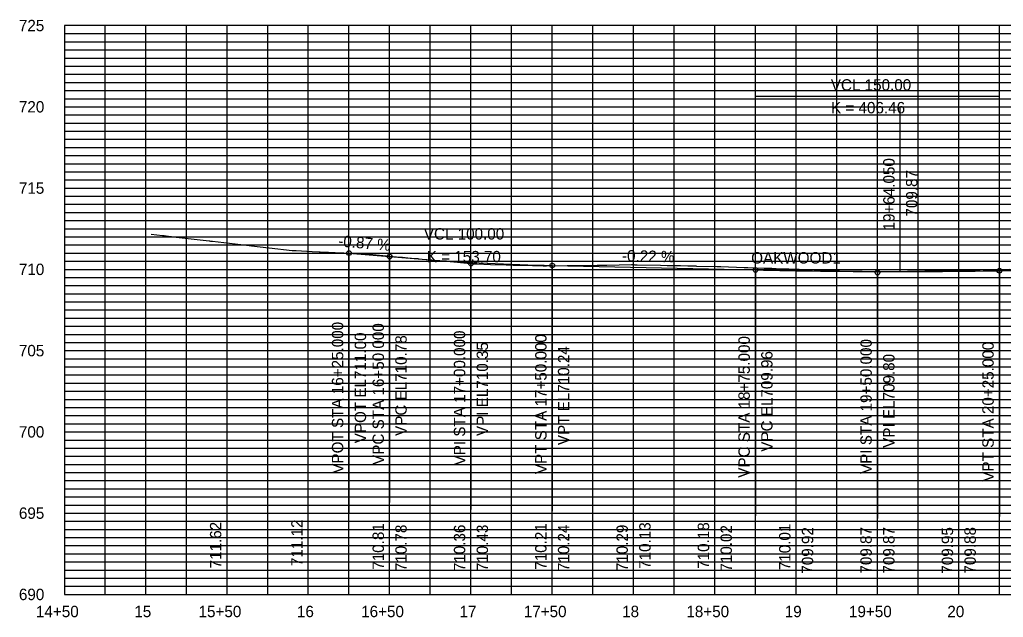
# Model space of a CAD drawing. Extents: x 599407 to 600507, y 234180 to 234548.
# Drawn here: x 599407 to 600012, y 234180 to 234548 of the extents above; entities that cross this region are included whole.
import ezdxf

# ---------------------------------------------------------------- set-up
doc = ezdxf.new("R2010")
doc.units = 0
for name, color, linetype in [('E_PROF_Grid', 7, 'Continuous'), ('E_PROF_GridMin', 7, 'Continuous'), ('P_E_XS_Ground', 7, 'Continuous'), ('P_PROF', 7, 'Continuous'), ('P_PROF_Grades', 7, 'Continuous'), ('P_PROF_VPINotes', 7, 'Continuous'), ('P_XS_Text', 7, 'Continuous'), ('PLT_Sheet_Info', 7, 'Continuous')]:
    doc.layers.add(name, color=color, linetype=linetype)

msp = doc.modelspace()

# ---------------------------------------------------------------- linework, layer by layer
at = {"layer": 'E_PROF_Grid'}
for p, q in [((599459.31, 234193.96), (599459.31, 234543.96)), ((599484.31, 234193.96), (599484.31, 234543.96)), ((599509.31, 234193.96), (599509.31, 234543.96)), ((599534.31, 234193.96), (599534.31, 234543.96)), ((599559.31, 234193.96), (599559.31, 234543.96)), ((599584.31, 234193.96), (599584.31, 234543.96)), ((599609.31, 234193.96), (599609.31, 234543.96)), ((599634.31, 234193.96), (599634.31, 234543.96)), ((599659.31, 234193.96), (599659.31, 234543.96)), ((599684.31, 234193.96), (599684.31, 234543.96)), ((599709.31, 234193.96), (599709.31, 234543.96)), ((599734.31, 234193.96), (599734.31, 234543.96)), ((599759.31, 234193.96), (599759.31, 234543.96)), ((599784.31, 234193.96), (599784.31, 234543.96)), ((599809.31, 234193.96), (599809.31, 234543.96)), ((599834.31, 234193.96), (599834.31, 234543.96)), ((599859.31, 234193.96), (599859.31, 234543.96)), ((599884.31, 234193.96), (599884.31, 234543.96)), ((599909.31, 234193.96), (599909.31, 234543.96)), ((599934.31, 234193.96), (599934.31, 234543.96)), ((599959.31, 234193.96), (599959.31, 234543.96)), ((599984.31, 234193.96), (599984.31, 234543.96)), ((600009.31, 234193.96), (600009.31, 234543.96)), ((599434.31, 234518.96), (600484.31, 234518.96)), ((599434.31, 234493.96), (600484.31, 234493.96)), ((599434.31, 234468.96), (600484.31, 234468.96)), ((599434.31, 234443.96), (600484.31, 234443.96)), ((599434.31, 234418.96), (600484.31, 234418.96)), ((599434.31, 234393.96), (600484.31, 234393.96)), ((599434.31, 234368.96), (600484.31, 234368.96)), ((599434.31, 234343.96), (600484.31, 234343.96)), ((599434.31, 234318.96), (600484.31, 234318.96)), ((599434.31, 234293.96), (600484.31, 234293.96)), ((599434.31, 234268.96), (600484.31, 234268.96)), ((599434.31, 234243.96), (600484.31, 234243.96)), ((599434.31, 234218.96), (600484.31, 234218.96))]:
    msp.add_line(p, q, dxfattribs=at)
at = {"layer": 'E_PROF_GridMin'}
for p, q in [((599434.31, 234538.96), (600484.31, 234538.96)), ((599434.31, 234533.96), (600484.31, 234533.96)), ((599434.31, 234528.96), (600484.31, 234528.96)), ((599434.31, 234523.96), (600484.31, 234523.96)), ((599434.31, 234513.96), (600484.31, 234513.96)), ((599434.31, 234508.96), (600484.31, 234508.96)), ((599434.31, 234503.96), (600484.31, 234503.96)), ((599434.31, 234498.96), (600484.31, 234498.96)), ((599434.31, 234488.96), (600484.31, 234488.96)), ((599434.31, 234483.96), (600484.31, 234483.96)), ((599434.31, 234478.96), (600484.31, 234478.96)), ((599434.31, 234473.96), (600484.31, 234473.96)), ((599434.31, 234463.96), (600484.31, 234463.96)), ((599434.31, 234458.96), (600484.31, 234458.96)), ((599434.31, 234453.96), (600484.31, 234453.96)), ((599434.31, 234448.96), (600484.31, 234448.96)), ((599434.31, 234438.96), (600484.31, 234438.96)), ((599434.31, 234433.96), (600484.31, 234433.96)), ((599434.31, 234428.96), (600484.31, 234428.96)), ((599434.31, 234423.96), (600484.31, 234423.96)), ((599434.31, 234413.96), (600484.31, 234413.96)), ((599434.31, 234408.96), (600484.31, 234408.96)), ((599434.31, 234403.96), (600484.31, 234403.96)), ((599434.31, 234398.96), (600484.31, 234398.96)), ((599434.31, 234388.96), (600484.31, 234388.96)), ((599434.31, 234383.96), (600484.31, 234383.96)), ((599434.31, 234378.96), (600484.31, 234378.96)), ((599434.31, 234373.96), (600484.31, 234373.96)), ((599434.31, 234363.96), (600484.31, 234363.96)), ((599434.31, 234358.96), (600484.31, 234358.96)), ((599434.31, 234353.96), (600484.31, 234353.96)), ((599434.31, 234348.96), (600484.31, 234348.96)), ((599434.31, 234338.96), (600484.31, 234338.96)), ((599434.31, 234333.96), (600484.31, 234333.96)), ((599434.31, 234328.96), (600484.31, 234328.96)), ((599434.31, 234323.96), (600484.31, 234323.96)), ((599434.31, 234313.96), (600484.31, 234313.96)), ((599434.31, 234308.96), (600484.31, 234308.96)), ((599434.31, 234303.96), (600484.31, 234303.96)), ((599434.31, 234298.96), (600484.31, 234298.96)), ((599434.31, 234288.96), (600484.31, 234288.96)), ((599434.31, 234283.96), (600484.31, 234283.96)), ((599434.31, 234278.96), (600484.31, 234278.96)), ((599434.31, 234273.96), (600484.31, 234273.96)), ((599434.31, 234263.96), (600484.31, 234263.96)), ((599434.31, 234258.96), (600484.31, 234258.96)), ((599434.31, 234253.96), (600484.31, 234253.96)), ((599434.31, 234248.96), (600484.31, 234248.96)), ((599434.31, 234238.96), (600484.31, 234238.96)), ((599434.31, 234233.96), (600484.31, 234233.96)), ((599434.31, 234228.96), (600484.31, 234228.96)), ((599434.31, 234223.96), (600484.31, 234223.96)), ((599434.31, 234213.96), (600484.31, 234213.96)), ((599434.31, 234208.96), (600484.31, 234208.96)), ((599434.31, 234203.96), (600484.31, 234203.96)), ((599434.31, 234198.96), (600484.31, 234198.96))]:
    msp.add_line(p, q, dxfattribs=at)
at = {"layer": 'P_E_XS_Ground'}
for p, q in [((599487.75, 234415.64), (599487.75, 234415.64)), ((599494.56, 234414.82), (599494.56, 234414.82)), ((599495.56, 234414.71), (599495.56, 234414.71)), ((599499.56, 234414.25), (599499.56, 234414.25)), ((599499.62, 234414.25), (599499.62, 234414.25)), ((599500.19, 234414.18), (599500.19, 234414.18)), ((599503.06, 234413.84), (599503.06, 234413.84)), ((599503.06, 234413.84), (599503.06, 234413.84)), ((599523.31, 234411.45), (599523.31, 234411.45)), ((599523.56, 234411.42), (599523.56, 234411.42)), ((599524.19, 234411.35), (599524.19, 234411.35)), ((599524.75, 234411.29), (599524.75, 234411.29)), ((599525.31, 234411.23), (599525.31, 234411.23)), ((599539.31, 234409.6), (599539.31, 234409.62)), ((599548, 234408.6), (599548, 234408.6)), ((599549.44, 234408.51), (599549.44, 234408.51)), ((599560.12, 234407.28), (599560.12, 234407.28)), ((599560.31, 234407.26), (599560.31, 234407.26)), ((599574.38, 234405.64), (599574.38, 234405.64)), ((599574.62, 234405.62), (599574.62, 234405.62)), ((599575.44, 234405.56), (599575.44, 234405.56)), ((599576, 234405.53), (599576, 234405.53)), ((599576.75, 234405.48), (599576.75, 234405.48)), ((599586.75, 234405), (599586.75, 234405)), ((599590.94, 234404.81), (599590.94, 234404.81)), ((599591.69, 234404.75), (599591.69, 234404.75)), ((599594.25, 234404.62), (599594.25, 234404.62)), ((599595.81, 234404.54), (599595.81, 234404.54)), ((599596.75, 234404.5), (599596.75, 234404.5)), ((599604.94, 234404.12), (599604.94, 234404.12)), ((599606.19, 234404.06), (599606.19, 234404.06)), ((599620.38, 234403.39), (599620.38, 234403.39)), ((599621.38, 234403.29), (599621.38, 234403.29)), ((599621.75, 234403.26), (599621.75, 234403.26)), ((599622.12, 234403.23), (599622.12, 234403.23)), ((599622.44, 234403.2), (599622.44, 234403.2)), ((599622.81, 234403.17), (599622.81, 234403.17)), ((599623.88, 234403.06), (599623.88, 234403.07)), ((599640.56, 234401.54), (599640.56, 234401.54)), ((599640.81, 234401.51), (599640.81, 234401.51)), ((599642.25, 234401.39), (599642.25, 234401.39)), ((599642.25, 234401.39), (599642.25, 234401.39)), ((599645.44, 234401.09), (599645.44, 234401.1)), ((599645.5, 234401.09), (599645.5, 234401.09)), ((599647.31, 234400.92), (599647.31, 234400.92)), ((599647.31, 234400.92), (599647.31, 234400.92)), ((599647.69, 234400.89), (599647.69, 234400.89)), ((599651.5, 234400.54), (599651.5, 234400.54)), ((599651.56, 234400.54), (599651.56, 234400.54)), ((599652.25, 234400.48), (599652.25, 234400.48)), ((599654.31, 234400.28), (599654.31, 234400.28)), ((599660.19, 234399.75), (599660.19, 234399.75)), ((599663.94, 234399.4), (599663.94, 234399.4)), ((599664.69, 234399.35), (599664.69, 234399.35)), ((599665.19, 234399.31), (599665.19, 234399.31)), ((599665.19, 234399.31), (599665.19, 234399.31)), ((599666.69, 234399.17), (599666.69, 234399.18)), ((599666.69, 234399.18), (599666.69, 234399.18)), ((599666.94, 234399.15), (599666.94, 234399.15)), ((599667.12, 234399.14), (599667.12, 234399.14)), ((599667.12, 234399.14), (599667.12, 234399.14)), ((599668.56, 234399.01), (599668.56, 234399.01)), ((599668.56, 234399.01), (599668.56, 234399.01)), ((599668.81, 234399), (599668.81, 234399)), ((599669, 234398.98), (599669, 234398.98)), ((599669, 234398.98), (599669, 234398.98)), ((599673.88, 234398.53), (599673.88, 234398.53)), ((599674, 234398.53), (599674, 234398.53)), ((599685.88, 234397.45), (599685.88, 234397.45)), ((599686.06, 234397.43), (599686.06, 234397.43)), ((599686.44, 234397.4), (599686.44, 234397.4)), ((599686.69, 234397.39), (599686.69, 234397.39)), ((599686.94, 234397.37), (599686.94, 234397.37)), ((599687.19, 234397.35), (599687.19, 234397.35)), ((599687.94, 234397.31), (599687.94, 234397.31)), ((599696.38, 234397.03), (599696.38, 234397.04)), ((599705.88, 234396.73), (599705.88, 234396.73)), ((599710.25, 234396.59), (599710.25, 234396.59)), ((599711, 234396.59), (599711, 234396.59)), ((599766.88, 234396.6), (599766.88, 234396.6)), ((599766.94, 234396.6), (599766.94, 234396.6)), ((599767.25, 234396.59), (599767.25, 234396.59)), ((599767.94, 234396.6), (599767.94, 234396.6)), ((599767.94, 234396.6), (599767.94, 234396.6)), ((599783.12, 234396.87), (599783.12, 234396.87)), ((599783.5, 234396.85), (599783.5, 234396.85)), ((599783.75, 234396.85), (599783.75, 234396.85)), ((599784, 234396.84), (599784, 234396.84)), ((599784.38, 234396.84), (599784.38, 234396.84)), ((599784.56, 234396.84), (599784.56, 234396.84)), ((599784.94, 234396.82), (599784.94, 234396.82)), ((599785.38, 234396.81), (599785.38, 234396.81)), ((599786.5, 234396.79), (599786.5, 234396.79)), ((599712.69, 234396.53), (599712.69, 234396.53)), ((599712.69, 234396.53), (599712.69, 234396.53)), ((599712.94, 234396.53), (599712.94, 234396.53)), ((599715, 234396.46), (599715, 234396.46)), ((599715.06, 234396.46), (599715.06, 234396.46)), ((599715.31, 234396.46), (599715.31, 234396.46)), ((599728.69, 234396.03), (599728.69, 234396.03)), ((599728.94, 234396.03), (599728.94, 234396.03)), ((599729.62, 234396.03), (599729.62, 234396.03)), ((599729.94, 234396.03), (599729.94, 234396.03)), ((599730.69, 234396.03), (599730.69, 234396.03)), ((599743.5, 234396.25), (599743.5, 234396.25)), ((599746.62, 234396.31), (599746.62, 234396.31)), ((599747.12, 234396.29), (599747.12, 234396.29)), ((599748.94, 234396.32), (599748.94, 234396.32)), ((599749, 234396.32), (599749, 234396.32)), ((599749.31, 234396.32), (599749.31, 234396.32)), ((599755.31, 234396.42), (599755.31, 234396.42)), ((599755.44, 234396.42), (599755.44, 234396.42)), ((599761.88, 234396.53), (599761.88, 234396.54)), ((599762.06, 234396.53), (599762.06, 234396.53)), ((599764, 234396.56), (599764, 234396.56)), ((599764.06, 234396.56), (599764.06, 234396.56)), ((599764.38, 234396.56), (599764.38, 234396.56)), ((599765.06, 234396.57), (599765.06, 234396.57)), ((599765.06, 234396.57), (599765.06, 234396.57)), ((599800.81, 234396.5), (599800.81, 234396.5)), ((599805, 234396.4), (599805, 234396.4)), ((599813.12, 234396.23), (599813.12, 234396.23)), ((599817.69, 234396.14), (599817.69, 234396.14)), ((599818.69, 234396.1), (599818.69, 234396.1)), ((599820.25, 234396.07), (599820.25, 234396.07)), ((599820.31, 234396.07), (599820.31, 234396.07)), ((599820.62, 234396.07), (599820.62, 234396.07)), ((599822.62, 234396.03), (599822.62, 234396.03)), ((599822.62, 234396.03), (599822.62, 234396.03)), ((599823, 234396.01), (599823, 234396.01)), ((599835.62, 234395.75), (599835.62, 234395.75)), ((599835.94, 234395.75), (599835.94, 234395.75)), ((599836.25, 234395.73), (599836.25, 234395.73)), ((599836.69, 234395.73), (599836.69, 234395.73)), ((599837.06, 234395.71), (599837.06, 234395.71)), ((599837.31, 234395.71), (599837.31, 234395.71)), ((599837.56, 234395.7), (599837.56, 234395.7)), ((599837.94, 234395.7), (599837.94, 234395.7)), ((599852.25, 234395.18), (599852.25, 234395.18)), ((599852.56, 234395.17), (599852.56, 234395.18)), ((599854.44, 234395.1), (599854.44, 234395.1)), ((599854.5, 234395.1), (599854.5, 234395.1)), ((599858.06, 234394.98), (599858.06, 234394.98)), ((599858.12, 234394.98), (599858.12, 234394.98)), ((599858.62, 234394.96), (599858.62, 234394.96)), ((599859.06, 234394.95), (599859.06, 234394.95)), ((599864.62, 234394.75), (599864.62, 234394.75)), ((599869.06, 234394.59), (599869.06, 234394.59)), ((599869.69, 234394.57), (599869.69, 234394.57)), ((599871.69, 234394.5), (599871.69, 234394.5)), ((599871.75, 234394.5), (599871.75, 234394.5)), ((599872, 234394.48), (599872, 234394.48)), ((599877, 234394.31), (599877, 234394.31)), ((599877.06, 234394.31), (599877.06, 234394.31)), ((599879.19, 234394.23), (599879.19, 234394.23)), ((599879.25, 234394.23), (599879.25, 234394.23)), ((599879.5, 234394.21), (599879.5, 234394.21)), ((599879.81, 234394.2), (599879.81, 234394.2)), ((599879.81, 234394.2), (599879.81, 234394.2)), ((599884.81, 234394.03), (599884.81, 234394.03)), ((599884.88, 234394.03), (599884.88, 234394.03)), ((599885.38, 234394), (599885.38, 234394.01)), ((599886.12, 234393.98), (599886.12, 234393.98)), ((599886.12, 234393.98), (599886.12, 234393.98)), ((599899.69, 234393.5), (599899.69, 234393.5)), ((599899.88, 234393.48), (599899.88, 234393.48)), ((599903.75, 234393.34), (599903.75, 234393.34)), ((599903.75, 234393.34), (599903.75, 234393.34)), ((599904, 234393.34), (599904, 234393.34)), ((599904.5, 234393.32), (599904.5, 234393.32)), ((599910.56, 234393.1), (599910.56, 234393.1)), ((599910.75, 234393.1), (599910.75, 234393.1)), ((599910.81, 234393.1), (599910.81, 234393.1)), ((599910.94, 234393.1), (599910.94, 234393.1)), ((599911, 234393.1), (599911, 234393.1)), ((599938.94, 234392.56), (599938.94, 234392.56)), ((599939, 234392.56), (599939, 234392.56)), ((599939.06, 234392.56), (599939.06, 234392.56)), ((599939.12, 234392.56), (599939.12, 234392.56)), ((599939.19, 234392.56), (599939.19, 234392.56)), ((599939.19, 234392.56), (599939.19, 234392.56)), ((599941.5, 234392.65), (599941.5, 234392.65)), ((599942.31, 234392.67), (599942.31, 234392.67)), ((599984.31, 234393.46), (599984.31, 234393.48)), ((599984.31, 234393.46), (599984.31, 234393.48)), ((599997.25, 234393.71), (599997.25, 234393.73)), ((599997.31, 234393.71), (599997.31, 234393.73)), ((599997.56, 234393.71), (599997.56, 234393.71))]:
    msp.add_line(p, q, dxfattribs=at)
msp.add_lwpolyline([(599487.75, 234415.64), (599494.56, 234414.82), (599495.56, 234414.71), (599499.56, 234414.25), (599499.62, 234414.25), (599500.19, 234414.18), (599503.06, 234413.84), (599503.06, 234413.84), (599523.31, 234411.45), (599523.56, 234411.42), (599524.19, 234411.35), (599524.75, 234411.29), (599525.31, 234411.23), (599539.31, 234409.6), (599548, 234408.6), (599549.44, 234408.51), (599560.12, 234407.28), (599560.31, 234407.26), (599574.38, 234405.64), (599574.62, 234405.62), (599575.44, 234405.56), (599576, 234405.53), (599576.75, 234405.48), (599586.75, 234405), (599590.94, 234404.81), (599591.69, 234404.75), (599594.25, 234404.62), (599595.81, 234404.54), (599596.75, 234404.5), (599604.94, 234404.12), (599606.19, 234404.06), (599620.38, 234403.39), (599621.38, 234403.29), (599621.75, 234403.26), (599622.12, 234403.23), (599622.44, 234403.2), (599622.81, 234403.17), (599623.88, 234403.06), (599640.56, 234401.54), (599640.81, 234401.51), (599642.25, 234401.39), (599642.25, 234401.39), (599645.44, 234401.09), (599645.5, 234401.09), (599647.31, 234400.92), (599647.31, 234400.92), (599647.69, 234400.89), (599651.5, 234400.54), (599651.56, 234400.54), (599652.25, 234400.48), (599654.31, 234400.28), (599660.19, 234399.75), (599663.94, 234399.4), (599664.69, 234399.35), (599665.19, 234399.31), (599665.19, 234399.31), (599666.69, 234399.18), (599666.69, 234399.17), (599666.94, 234399.15), (599667.12, 234399.14), (599667.12, 234399.14), (599668.56, 234399.01), (599668.56, 234399.01), (599668.81, 234399), (599669, 234398.98), (599669, 234398.98), (599673.88, 234398.53), (599674, 234398.53), (599685.88, 234397.45), (599686.06, 234397.43), (599686.44, 234397.4), (599686.69, 234397.39), (599686.94, 234397.37), (599687.19, 234397.35), (599687.94, 234397.31), (599696.38, 234397.03), (599705.88, 234396.73), (599710.25, 234396.59), (599711, 234396.59), (599712.69, 234396.53), (599712.69, 234396.53), (599712.94, 234396.53), (599715, 234396.46), (599715.06, 234396.46), (599715.31, 234396.46), (599728.69, 234396.03), (599728.94, 234396.03), (599729.62, 234396.03), (599729.94, 234396.03), (599730.69, 234396.03), (599743.5, 234396.25), (599746.62, 234396.31), (599747.12, 234396.29), (599748.94, 234396.32), (599749, 234396.32), (599749.31, 234396.32), (599755.31, 234396.42), (599755.44, 234396.42), (599761.88, 234396.53), (599762.06, 234396.53), (599764, 234396.56), (599764.06, 234396.56), (599764.38, 234396.56), (599765.06, 234396.57), (599765.06, 234396.57), (599766.88, 234396.6), (599766.94, 234396.6), (599767.25, 234396.59), (599767.94, 234396.6), (599767.94, 234396.6), (599783.12, 234396.87), (599783.5, 234396.85), (599783.75, 234396.85), (599784, 234396.84), (599784.38, 234396.84), (599784.56, 234396.84), (599784.94, 234396.82), (599785.38, 234396.81), (599786.5, 234396.79), (599800.81, 234396.5), (599805, 234396.4), (599813.12, 234396.23), (599817.69, 234396.14), (599818.69, 234396.1), (599820.25, 234396.07), (599820.31, 234396.07), (599820.62, 234396.07), (599822.62, 234396.03), (599822.62, 234396.03), (599823, 234396.01), (599835.62, 234395.75), (599835.94, 234395.75), (599836.25, 234395.73), (599836.69, 234395.73), (599837.06, 234395.71), (599837.31, 234395.71), (599837.56, 234395.7), (599837.94, 234395.7), (599852.25, 234395.18), (599852.56, 234395.17), (599854.44, 234395.1), (599854.5, 234395.1), (599858.06, 234394.98), (599858.12, 234394.98), (599858.62, 234394.96), (599859.06, 234394.95), (599864.62, 234394.75), (599869.06, 234394.59), (599869.69, 234394.57), (599871.69, 234394.5), (599871.75, 234394.5), (599872, 234394.48), (599877, 234394.31), (599877.06, 234394.31), (599879.19, 234394.23), (599879.25, 234394.23), (599879.5, 234394.21), (599879.81, 234394.2), (599879.81, 234394.2), (599884.81, 234394.03), (599884.88, 234394.03), (599885.38, 234394), (599886.12, 234393.98), (599886.12, 234393.98), (599899.69, 234393.5), (599899.88, 234393.48), (599903.75, 234393.34), (599903.75, 234393.34), (599904, 234393.34), (599904.5, 234393.32), (599910.56, 234393.1), (599910.75, 234393.1), (599910.81, 234393.1), (599910.94, 234393.1), (599911, 234393.1), (599938.94, 234392.56), (599939, 234392.56), (599939.06, 234392.56), (599939.12, 234392.56), (599939.19, 234392.56), (599939.19, 234392.56), (599941.5, 234392.65), (599942.31, 234392.67), (599984.31, 234393.46), (599984.31, 234393.46), (599997.25, 234393.71), (599997.31, 234393.71), (599997.56, 234393.71), (600015.44, 234394.09)], dxfattribs=at)
at = {"layer": 'P_PROF'}
msp.add_lwpolyline([(599609.31, 234403.96), (599634.31, 234401.79), (599639.31, 234401.37), (599644.31, 234400.95), (599649.31, 234400.56), (599654.31, 234400.18), (599659.31, 234399.82), (599664.31, 234399.48), (599669.31, 234399.15), (599674.31, 234398.84), (599679.31, 234398.54), (599684.31, 234398.26), (599689.31, 234398), (599694.31, 234397.75), (599699.31, 234397.51), (599704.31, 234397.29), (599709.31, 234397.1), (599714.31, 234396.92), (599719.31, 234396.75), (599724.31, 234396.6), (599729.31, 234396.46), (599734.31, 234396.35), (599734.31, 234396.35), (599734.31, 234396.35), (599859.31, 234393.6), (599864.31, 234393.5), (599869.31, 234393.4), (599874.31, 234393.31), (599879.31, 234393.21), (599884.31, 234393.14), (599889.31, 234393.06), (599894.31, 234393), (599899.31, 234392.93), (599904.31, 234392.87), (599909.31, 234392.82), (599914.31, 234392.78), (599919.31, 234392.73), (599924.31, 234392.7), (599929.31, 234392.68), (599934.31, 234392.65), (599939.31, 234392.64), (599944.31, 234392.64), (599949.31, 234392.64), (599954.31, 234392.64), (599959.31, 234392.65), (599964.31, 234392.67), (599969.31, 234392.68), (599974.31, 234392.71), (599979.31, 234392.75), (599984.31, 234392.79), (599989.31, 234392.84), (599994.31, 234392.89), (599999.31, 234392.95), (600004.31, 234393.01), (600009.31, 234393.09), (600009.31, 234393.09), (600009.31, 234393.09), (600084.38, 234394.21)], dxfattribs=at)
for centre in [(599609.34, 234403.96), (599634.34, 234401.79), (599684.34, 234397.43), (599734.34, 234396.34), (599859.34, 234393.6), (599934.34, 234391.96), (600009.34, 234393.09)]:
    msp.add_circle(centre, 1.41, dxfattribs=at)
at = {"layer": 'P_PROF_Grades'}
for p, q in [((599534.31, 234193.96), (599534.31, 234252.76)), ((599584.31, 234193.96), (599584.31, 234252.76)), ((599634.31, 234193.96), (599634.31, 234252.76)), ((599634.31, 234193.96), (599634.31, 234252.76)), ((599634.31, 234193.96), (599634.31, 234252.76)), ((599684.31, 234193.96), (599684.31, 234252.76)), ((599684.31, 234193.96), (599684.31, 234252.76)), ((599734.31, 234193.96), (599734.31, 234252.76)), ((599734.31, 234193.96), (599734.31, 234252.76)), ((599734.31, 234193.96), (599734.31, 234252.76)), ((599784.31, 234193.96), (599784.31, 234252.76)), ((599784.31, 234193.96), (599784.31, 234252.76)), ((599834.31, 234193.96), (599834.31, 234252.76)), ((599834.31, 234193.96), (599834.31, 234252.76)), ((599884.31, 234193.96), (599884.31, 234252.76)), ((599884.31, 234193.96), (599884.31, 234252.76)), ((599934.31, 234193.96), (599934.31, 234252.76)), ((599934.31, 234193.96), (599934.31, 234252.76)), ((599984.31, 234193.96), (599984.31, 234252.76)), ((599984.31, 234193.96), (599984.31, 234252.76)), ((599984.31, 234193.96), (599984.31, 234252.76)), ((599984.31, 234193.96), (599984.31, 234252.76))]:
    msp.add_line(p, q, dxfattribs=at)
at = {"layer": 'P_PROF_VPINotes'}
for p, q in [((599859.31, 234493.43), (599859.31, 234507.43)), ((600009.31, 234493.43), (600009.31, 234507.43)), ((599859.31, 234500.43), (600009.31, 234500.43)), ((599948.38, 234392.64), (599948.38, 234493.43)), ((599634.31, 234401.79), (599634.31, 234415.79)), ((599734.31, 234401.79), (599734.31, 234415.79)), ((599634.31, 234408.79), (599734.31, 234408.79)), ((599609.31, 234403.96), (599609.31, 234244.37)), ((599634.31, 234401.79), (599634.31, 234250.59)), ((599684.31, 234397.45), (599684.31, 234246.25)), ((599734.31, 234396.35), (599734.31, 234245.15)), ((599859.31, 234393.6), (599859.31, 234242.4)), ((599934.31, 234391.96), (599934.31, 234240.76)), ((600009.31, 234393.09), (600009.31, 234241.89))]:
    msp.add_line(p, q, dxfattribs=at)
at = {"layer": 'PLT_Sheet_Info'}
msp.add_lwpolyline([(599434.31, 234193.96), (600484.31, 234193.96), (600484.31, 234543.96), (599434.31, 234543.96), (599434.31, 234193.96)], dxfattribs=at)

# ---------------------------------------------------------------- texts
at = {"layer": 'P_PROF_Grades'}
for s, p in [('725', (599406.31, 234540.46)), ('720', (599406.31, 234490.46)), ('715', (599406.31, 234440.46)), ('710', (599406.31, 234390.46)), ('705', (599406.31, 234340.46)), ('700', (599406.31, 234290.46)), ('695', (599406.31, 234240.46)), ('690', (599406.31, 234190.46)), ('14+50', (599416.81, 234179.96)), ('15', (599477.31, 234179.96)), ('15+50', (599516.81, 234179.96)), ('16', (599577.31, 234179.96)), ('16+50', (599616.81, 234179.96)), ('17', (599677.31, 234179.96)), ('17+50', (599716.81, 234179.96)), ('18', (599777.31, 234179.96)), ('18+50', (599816.81, 234179.96)), ('19', (599877.31, 234179.96)), ('19+50', (599916.81, 234179.96)), ('20', (599977.31, 234179.96))]:
    msp.add_text(s, height=7, dxfattribs=at).set_placement(p)
for s, rotation, p in [('-0.87 %', 355.02945, (599602.47, 234408.08)), ('-0.22 %', 358.74492, (599777.15, 234398.91)), ('711.12', 90, (599580.81, 234211.41)), ('711.62', 90, (599530.81, 234209.98)), ('710.81', 90, (599630.81, 234209.15)), ('710.78', 90, (599644.81, 234208.27)), ('710.78', 90, (599644.81, 234208.27)), ('710.36', 90, (599680.81, 234208.27)), ('710.43', 90, (599694.81, 234208.27)), ('710.21', 90, (599730.81, 234209.15)), ('710.24', 90, (599744.81, 234208.27)), ('710.24', 90, (599744.81, 234208.27)), ('710.29', 90, (599780.81, 234208.27)), ('710.13', 90, (599794.81, 234209.7)), ('710.18', 90, (599830.81, 234209.7)), ('710.02', 90, (599844.81, 234207.99)), ('710.01', 90, (599880.81, 234208.88)), ('709.92', 90, (599894.81, 234206.73)), ('709.87', 90, (599930.81, 234206.78)), ('709.87', 90, (599944.81, 234206.78)), ('709.95', 90, (599980.81, 234206.73)), ('709.95', 90, (599980.81, 234206.73)), ('709.95', 90, (599980.81, 234206.73)), ('709.88', 90, (599994.81, 234206.78))]:
    msp.add_text(s, height=7, rotation=rotation, dxfattribs=at).set_placement(p)
at = {"layer": 'P_PROF_VPINotes'}
for s, rotation, p in [('VCL 150.00', 0, (599905.63, 234503.93)), ('K = 406.46', 0, (599905.77, 234489.93)), ('19+64.050', 90, (599944.88, 234417.87)), ('709.87', 90, (599958.88, 234426.44)), ('VCL 100.00', 0, (599655.35, 234412.29)), ('K = 153.70', 0, (599657.17, 234398.29)), ('VPOT STA 16+25.000', 90, (599605.81, 234268.26)), ('VPC STA 16+50.000', 90, (599630.81, 234273.65)), ('VPOT EL711.00', 90, (599619.81, 234286.94)), ('VPI STA 17+00.000', 90, (599680.81, 234273.31)), ('VPC EL710.78', 90, (599644.81, 234291.48)), ('VPI EL710.35', 90, (599694.81, 234291.42)), ('VPT STA 17+50.000', 90, (599730.81, 234267.97)), ('VPC STA 18+75.000', 90, (599855.81, 234265.74)), ('VPI STA 19+50.000', 90, (599930.81, 234268.06)), ('VPT STA 20+25.000', 90, (600005.81, 234263.29)), ('VPT EL710.24', 90, (599744.81, 234285.8)), ('VPC EL709.96', 90, (599869.81, 234281.75)), ('VPI EL709.80', 90, (599944.81, 234284.16))]:
    msp.add_text(s, height=7, rotation=rotation, dxfattribs=at).set_placement(p)
at = {"layer": 'P_XS_Text'}
msp.add_text('OAKWOOD1', height=7, rotation=0.02945, dxfattribs=at).set_placement((599856.67, 234397.52))

doc.saveas('drawing.dxf')
